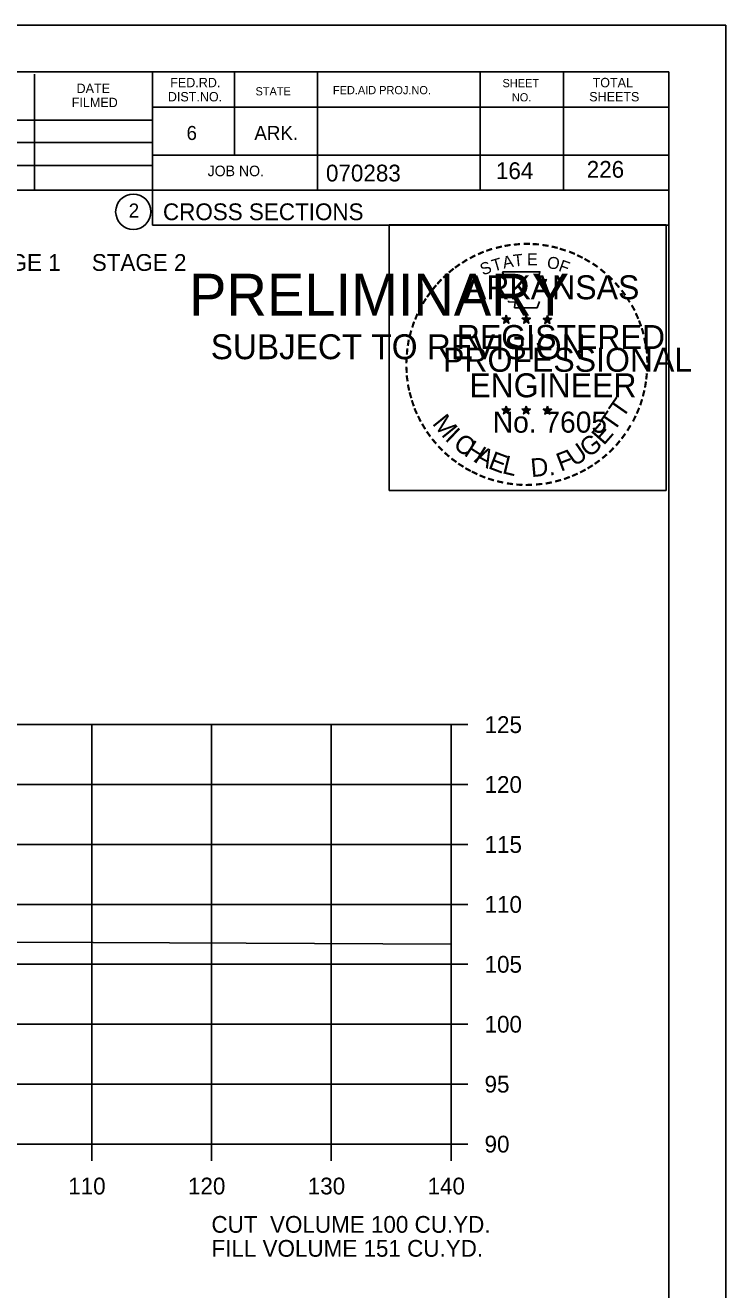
# Model space of a CAD drawing. Extents: x 1175611 to 1176402, y -433344 to -416213.
# Drawn here: x 1175885.4 to 1175943.9, y -429609 to -429503.4 of the extents above; entities that cross this region are included whole.
import ezdxf

# ---------------------------------------------------------------- set-up
doc = ezdxf.new("R2010")
doc.units = 0
for name, color, linetype in [('Default', 7, 'Continuous'), ('R_Axis', 7, 'Continuous'), ('R_Axis Annot', 7, 'Continuous'), ('R_Border', 7, 'Continuous'), ('R_Border Notes', 7, 'Continuous'), ('R_Border PE', 7, 'Continuous'), ('R_Border Prem', 7, 'Continuous'), ('R_Exist Surface', 7, 'Continuous'), ('R_Grid', 7, 'Continuous'), ('R_No Plot', 7, 'Continuous')]:
    doc.layers.add(name, color=color, linetype=linetype)

msp = doc.modelspace()

# ---------------------------------------------------------------- linework, layer by layer
at = {"layer": 'R_Axis'}
for p, q in [((1175920.97, -429596.8), (1175920.97, -429561.8)), ((1175922.37, -429561.8), (1175920.97, -429561.8)), ((1175922.37, -429566.8), (1175920.97, -429566.8)), ((1175922.37, -429571.8), (1175920.97, -429571.8)), ((1175922.37, -429576.8), (1175920.97, -429576.8)), ((1175922.37, -429581.8), (1175920.97, -429581.8)), ((1175922.37, -429586.8), (1175920.97, -429586.8)), ((1175922.37, -429591.8), (1175920.97, -429591.8)), ((1175640.97, -429596.8), (1175920.97, -429596.8)), ((1175890.97, -429598.2), (1175890.97, -429596.8)), ((1175900.97, -429598.2), (1175900.97, -429596.8)), ((1175910.97, -429598.2), (1175910.97, -429596.8)), ((1175920.97, -429598.2), (1175920.97, -429596.8)), ((1175922.37, -429596.8), (1175920.97, -429596.8))]:
    msp.add_line(p, q, dxfattribs=at)
at = {"layer": 'R_Border'}
for p, q in [((1175622.97, -429507.34), (1175939.15, -429507.34)), ((1175886.19, -429517.22), (1175886.19, -429507.54)), ((1175896.05, -429507.34), (1175896.05, -429520.14)), ((1175902.89, -429507.34), (1175902.89, -429514.28)), ((1175909.83, -429507.34), (1175909.83, -429517.22)), ((1175923.41, -429507.34), (1175923.41, -429517.22)), ((1175930.35, -429507.34), (1175930.35, -429517.22)), ((1175939.15, -429712.8), (1175939.15, -429507.34)), ((1175939.15, -429510.28), (1175896.05, -429510.28)), ((1175939.15, -429510.26), (1175939.15, -429510.26)), ((1175856.89, -429511.36), (1175896.05, -429511.36)), ((1175856.89, -429513.22), (1175896.05, -429513.22)), ((1175939.15, -429514.28), (1175896.05, -429514.28)), ((1175899.01, -429514.28), (1175939.15, -429514.28)), ((1175856.89, -429515.16), (1175896.05, -429515.16)), ((1175939.15, -429517.22), (1175856.89, -429517.22)), ((1175896.05, -429520.14), (1175939.15, -429520.14))]:
    msp.add_line(p, q, dxfattribs=at)
msp.add_circle((1175894.44, -429519.01), 1.47, dxfattribs=at)
at = {"layer": 'R_Border PE'}
for p, q in [((1175925.23, -429527.9), (1175925.58, -429528.01)), ((1175925.23, -429527.9), (1175925.49, -429527.94)), ((1175925.23, -429527.9), (1175925.47, -429528.02)), ((1175925.37, -429528.31), (1175925.58, -429528.01)), ((1175925.37, -429528.31), (1175925.49, -429528.06)), ((1175925.58, -429527.64), (1175925.54, -429527.9)), ((1175925.58, -429528.01), (1175925.58, -429527.64)), ((1175925.58, -429527.64), (1175925.63, -429527.89)), ((1175925.93, -429527.9), (1175925.58, -429528.01)), ((1175925.8, -429528.31), (1175925.58, -429528.01)), ((1175925.93, -429527.9), (1175925.64, -429527.95)), ((1175925.8, -429528.31), (1175925.66, -429528.01)), ((1175925.93, -429527.9), (1175925.73, -429528)), ((1175926.9, -429527.9), (1175927.25, -429528.01)), ((1175926.9, -429527.9), (1175927.16, -429527.94)), ((1175926.9, -429527.9), (1175927.14, -429528.02)), ((1175927.04, -429528.31), (1175927.25, -429528.01)), ((1175927.04, -429528.31), (1175927.16, -429528.06)), ((1175927.25, -429527.64), (1175927.21, -429527.9)), ((1175927.25, -429528.01), (1175927.25, -429527.64)), ((1175927.25, -429527.64), (1175927.3, -429527.89)), ((1175927.6, -429527.9), (1175927.25, -429528.01)), ((1175927.47, -429528.31), (1175927.25, -429528.01)), ((1175927.6, -429527.9), (1175927.31, -429527.95)), ((1175927.47, -429528.31), (1175927.33, -429528.01)), ((1175927.6, -429527.9), (1175927.4, -429528)), ((1175928.67, -429527.91), (1175929.02, -429528.02)), ((1175928.67, -429527.91), (1175928.92, -429527.95)), ((1175928.67, -429527.91), (1175928.91, -429528.03)), ((1175928.8, -429528.32), (1175929.02, -429528.02)), ((1175929.02, -429527.66), (1175928.98, -429527.91)), ((1175929.02, -429528.02), (1175929.02, -429527.66)), ((1175929.02, -429527.66), (1175929.07, -429527.91)), ((1175929.36, -429527.91), (1175929.02, -429528.02)), ((1175929.23, -429528.32), (1175929.02, -429528.02)), ((1175929.36, -429527.91), (1175929.08, -429527.96)), ((1175929.23, -429528.32), (1175929.09, -429528.03)), ((1175929.36, -429527.91), (1175929.16, -429528.01)), ((1175925.37, -429528.31), (1175925.58, -429528.09)), ((1175925.8, -429528.31), (1175925.58, -429528.09)), ((1175927.04, -429528.31), (1175927.25, -429528.09)), ((1175927.47, -429528.31), (1175927.25, -429528.09)), ((1175928.8, -429528.32), (1175928.93, -429528.07)), ((1175928.8, -429528.32), (1175929.02, -429528.1)), ((1175929.23, -429528.32), (1175929.02, -429528.1)), ((1175925.58, -429535.22), (1175925.54, -429535.47)), ((1175925.58, -429535.58), (1175925.58, -429535.22)), ((1175925.58, -429535.22), (1175925.63, -429535.47)), ((1175927.25, -429535.22), (1175927.21, -429535.47)), ((1175927.25, -429535.58), (1175927.25, -429535.22)), ((1175927.25, -429535.22), (1175927.3, -429535.47)), ((1175929.02, -429535.23), (1175928.97, -429535.48)), ((1175929.02, -429535.59), (1175929.02, -429535.23)), ((1175929.02, -429535.23), (1175929.06, -429535.48)), ((1175925.23, -429535.47), (1175925.58, -429535.58)), ((1175925.23, -429535.47), (1175925.48, -429535.52)), ((1175925.23, -429535.47), (1175925.47, -429535.59)), ((1175925.36, -429535.88), (1175925.58, -429535.58)), ((1175925.36, -429535.88), (1175925.49, -429535.63)), ((1175925.36, -429535.88), (1175925.58, -429535.66)), ((1175925.93, -429535.47), (1175925.58, -429535.58)), ((1175925.79, -429535.88), (1175925.58, -429535.58)), ((1175925.79, -429535.88), (1175925.58, -429535.66)), ((1175925.93, -429535.47), (1175925.64, -429535.52)), ((1175925.79, -429535.88), (1175925.66, -429535.59)), ((1175925.93, -429535.47), (1175925.72, -429535.57)), ((1175926.9, -429535.47), (1175927.25, -429535.58)), ((1175926.9, -429535.47), (1175927.15, -429535.52)), ((1175926.9, -429535.47), (1175927.14, -429535.59)), ((1175927.03, -429535.88), (1175927.25, -429535.58)), ((1175927.03, -429535.88), (1175927.16, -429535.63)), ((1175927.03, -429535.88), (1175927.25, -429535.66)), ((1175927.6, -429535.47), (1175927.25, -429535.58)), ((1175927.46, -429535.88), (1175927.25, -429535.58)), ((1175927.46, -429535.88), (1175927.25, -429535.66)), ((1175927.6, -429535.47), (1175927.31, -429535.52)), ((1175927.46, -429535.88), (1175927.32, -429535.59)), ((1175927.6, -429535.47), (1175927.39, -429535.57)), ((1175928.67, -429535.48), (1175929.02, -429535.59)), ((1175928.67, -429535.48), (1175928.92, -429535.53)), ((1175928.67, -429535.48), (1175928.9, -429535.6)), ((1175928.8, -429535.89), (1175929.02, -429535.59)), ((1175928.8, -429535.89), (1175928.93, -429535.64)), ((1175928.8, -429535.89), (1175929.01, -429535.67)), ((1175929.23, -429535.89), (1175929.01, -429535.67)), ((1175929.36, -429535.48), (1175929.02, -429535.59)), ((1175929.23, -429535.89), (1175929.02, -429535.59)), ((1175929.36, -429535.48), (1175929.08, -429535.53)), ((1175929.23, -429535.89), (1175929.09, -429535.6)), ((1175929.36, -429535.48), (1175929.16, -429535.58))]:
    msp.add_line(p, q, dxfattribs=at)
for points in [[(1175925.28, -429524.02), (1175925.54, -429524.85)], [(1175928.79, -429524.94), (1175928.93, -429524.66), (1175928.24, -429524.68), (1175928.39, -429524.02), (1175925.28, -429524.02)], [(1175925.77, -429526.44), (1175925.77, -429526.53), (1175926.33, -429526.55), (1175926.28, -429527.02), (1175928.15, -429527.02), (1175928.35, -429526.49)], [(1175925.58, -429527.64), (1175925.8, -429528.31), (1175925.23, -429527.9), (1175925.93, -429527.9), (1175925.37, -429528.31), (1175925.58, -429527.64)], [(1175927.25, -429527.64), (1175927.47, -429528.31), (1175926.9, -429527.9), (1175927.6, -429527.9), (1175927.04, -429528.31), (1175927.25, -429527.64)], [(1175929.02, -429527.66), (1175929.23, -429528.32), (1175928.67, -429527.91), (1175929.36, -429527.91), (1175928.8, -429528.32), (1175929.02, -429527.66)], [(1175925.58, -429535.22), (1175925.79, -429535.88), (1175925.23, -429535.47), (1175925.93, -429535.47), (1175925.36, -429535.88), (1175925.58, -429535.22)], [(1175927.25, -429535.22), (1175927.46, -429535.88), (1175926.9, -429535.47), (1175927.6, -429535.47), (1175927.03, -429535.88), (1175927.25, -429535.22)], [(1175929.02, -429535.23), (1175929.23, -429535.89), (1175928.67, -429535.48), (1175929.36, -429535.48), (1175928.8, -429535.89), (1175929.02, -429535.23)]]:
    msp.add_lwpolyline(points, dxfattribs=at)
for centre, radius in [((1175925.58, -429528.01), 0.172), ((1175925.58, -429528.01), 0.145), ((1175925.58, -429528.01), 0.116), ((1175925.58, -429528.01), 0.0991), ((1175925.58, -429528.01), 0.0747), ((1175925.58, -429528.01), 0.0495), ((1175925.58, -429528.01), 0.0296), ((1175927.25, -429528.01), 0.172), ((1175927.25, -429528.01), 0.145), ((1175927.25, -429528.01), 0.116), ((1175927.25, -429528.01), 0.0991), ((1175927.25, -429528.01), 0.0747), ((1175927.25, -429528.01), 0.0495), ((1175927.25, -429528.01), 0.0296), ((1175929.02, -429528.02), 0.172), ((1175929.02, -429528.02), 0.145), ((1175929.02, -429528.02), 0.116), ((1175929.02, -429528.02), 0.0991), ((1175929.02, -429528.02), 0.0747), ((1175929.02, -429528.02), 0.0495), ((1175929.02, -429528.02), 0.0296), ((1175925.58, -429535.58), 0.172), ((1175925.58, -429535.58), 0.145), ((1175927.25, -429535.58), 0.172), ((1175927.25, -429535.58), 0.145), ((1175929.01, -429535.59), 0.172), ((1175929.01, -429535.59), 0.145), ((1175925.58, -429535.58), 0.116), ((1175925.58, -429535.58), 0.0991), ((1175925.58, -429535.58), 0.0747), ((1175925.58, -429535.58), 0.0495), ((1175925.58, -429535.58), 0.0296), ((1175927.25, -429535.58), 0.116), ((1175927.25, -429535.58), 0.0991), ((1175927.25, -429535.58), 0.0747), ((1175927.25, -429535.58), 0.0495), ((1175927.25, -429535.58), 0.0296), ((1175929.01, -429535.59), 0.116), ((1175929.01, -429535.59), 0.0991), ((1175929.01, -429535.59), 0.0747), ((1175929.01, -429535.59), 0.0495), ((1175929.01, -429535.59), 0.0296)]:
    msp.add_circle(centre, radius, dxfattribs=at)
at = {"layer": 'R_Exist Surface'}
msp.add_lwpolyline([(1175827.66, -429580.31), (1175828.73, -429580.43), (1175841.16, -429581.94), (1175848.1, -429580.68), (1175852.72, -429579.81), (1175903.88, -429580.04), (1175920.97, -429580.12)], dxfattribs=at)
at = {"layer": 'R_Grid'}
for p, q in [((1175640.97, -429561.8), (1175920.97, -429561.8)), ((1175890.97, -429596.8), (1175890.97, -429561.8)), ((1175900.97, -429596.8), (1175900.97, -429561.8)), ((1175910.97, -429596.8), (1175910.97, -429561.8)), ((1175920.97, -429596.8), (1175920.97, -429561.8)), ((1175640.97, -429566.8), (1175920.97, -429566.8)), ((1175640.97, -429571.8), (1175920.97, -429571.8)), ((1175640.97, -429576.8), (1175920.97, -429576.8)), ((1175640.97, -429581.8), (1175920.97, -429581.8)), ((1175640.97, -429586.8), (1175920.97, -429586.8)), ((1175640.97, -429591.8), (1175920.97, -429591.8)), ((1175640.97, -429596.8), (1175920.97, -429596.8))]:
    msp.add_line(p, q, dxfattribs=at)
at = {"layer": 'R_No Plot'}
msp.add_line((1175610.57, -429503.45), (1175943.91, -429503.45), dxfattribs=at)
for points in [[(1175610.57, -429503.45), (1175943.91, -429503.45), (1175943.91, -429716.79), (1175610.57, -429716.79)], [(1175915.82, -429520.11), (1175938.92, -429520.11), (1175938.92, -429542.26), (1175915.82, -429542.26)]]:
    msp.add_lwpolyline(points, close=True, dxfattribs=at)

# ---------------------------------------------------------------- texts
at = {"layer": 'Default'}
for s, p in [('STAGE 1     STAGE 2', (1175880.47, -429523.94)), ('CUT  VOLUME 100 CU.YD.', (1175900.97, -429604.2)), ('FILL VOLUME 151 CU.YD.', (1175900.97, -429606.2))]:
    msp.add_text(s, height=1.4, dxfattribs=at).set_placement(p)
at = {"layer": 'R_Axis Annot'}
for s, p in [('125', (1175923.77, -429562.5)), ('120', (1175923.77, -429567.5)), ('115', (1175923.77, -429572.5)), ('110', (1175923.77, -429577.5)), ('105', (1175923.77, -429582.5)), ('100', (1175923.77, -429587.5)), ('95', (1175923.77, -429592.5)), ('90', (1175923.77, -429597.5)), ('110', (1175889.01, -429601)), ('120', (1175899.01, -429601)), ('130', (1175909.01, -429601)), ('140', (1175919.01, -429601))]:
    msp.add_text(s, height=1.4, dxfattribs=at).set_placement(p)
at = {"layer": 'R_Border'}
for s, height, p in [('FED.RD.', 0.782, (1175897.53, -429508.62)), ('SHEET', 0.684, (1175925.27, -429508.62)), ('TOTAL', 0.782, (1175932.79, -429508.62)), ('DATE', 0.782, (1175889.71, -429509.1)), ('DIST.NO.', 0.782, (1175897.33, -429509.8)), ('STATE', 0.684, (1175904.65, -429509.3)), ('FED.AID PROJ.NO.', 0.684, (1175911.11, -429509.2)), ('SHEETS', 0.782, (1175932.51, -429509.8)), ('FILMED', 0.782, (1175889.31, -429510.28)), ('NO.', 0.684, (1175926.05, -429509.8)), ('6', 1.17, (1175898.89, -429513.02)), ('ARK.', 1.172, (1175904.55, -429513.02)), ('JOB NO.', 0.879, (1175900.65, -429516.04)), ('070283', 1.4, (1175910.53, -429516.48)), ('2', 1.17, (1175894.06, -429519.49)), ('CROSS SECTIONS', 1.4, (1175896.92, -429519.71))]:
    msp.add_text(s, height=height, rotation=360, dxfattribs=at).set_placement(p)
at = {"layer": 'R_Border Notes'}
for s, p in [('164', (1175924.72, -429516.28)), ('226', (1175932.3, -429516.17))]:
    msp.add_text(s, height=1.4, dxfattribs=at).set_placement(p)
at = {"layer": 'R_Border PE'}
for s, height, rotation, p in [('-', 1.6, 10.2193, (1175925.45, -429522.49)), ('-', 1.6, 5.8968, (1175926.18, -429522.38)), ('-', 1.6, 0.1862, (1175926.95, -429522.31)), ('-', 1.6, 357.743, (1175927.67, -429522.32)), ('-', 1.6, 352.1617, (1175928.42, -429522.38)), ('-', 1.6, 28.7918, (1175922.76, -429523.48)), ('-', 1.6, 24.3072, (1175923.39, -429523.16)), ('-', 1.6, 19.1761, (1175924.02, -429522.89)), ('-', 1.6, 13.6301, (1175924.77, -429522.65)), ('A', 1, 11.2132, (1175925.37, -429523.76)), ('T', 1, 6.0228, (1175926.22, -429523.59)), ('E', 1, 0.8323, (1175927.32, -429523.48)), ('O', 1, 350.4515, (1175928.93, -429523.69)), ('-', 1.6, 347.2049, (1175929.14, -429522.49)), ('-', 1.6, 342.3362, (1175929.77, -429522.65)), ('-', 1.6, 337.8551, (1175930.51, -429522.87)), ('-', 1.6, 334.1211, (1175931.14, -429523.14)), ('-', 1.6, 38.9507, (1175921.1, -429524.62)), ('-', 1.6, 36.2317, (1175921.58, -429524.24)), ('-', 1.6, 34.0636, (1175922.16, -429523.85)), ('S', 1, 21.594, (1175923.63, -429524.34)), ('T', 1, 16.4036, (1175924.54, -429524.01)), ('F', 1, 340.0707, (1175929.88, -429523.92)), ('-', 1.6, 329.6409, (1175931.72, -429523.42)), ('-', 1.6, 325.8627, (1175932.36, -429523.78)), ('-', 1.6, 320.5297, (1175932.97, -429524.21)), ('-', 1.6, 48.423, (1175920.22, -429525.52)), ('-', 1.6, 42.9622, (1175920.67, -429525.04)), ('ARKANSAS', 2, 360, (1175922.13, -429526.31)), ('-', 1.6, 315.5786, (1175933.57, -429524.7)), ('-', 1.6, 309.8797, (1175934.14, -429525.25)), ('-', 1.6, 54.2325, (1175919.41, -429526.57)), ('-', 1.6, 50.6142, (1175919.82, -429526)), ('-', 1.6, 306.6522, (1175934.66, -429525.85)), ('-', 1.6, 62.8713, (1175918.77, -429527.71)), ('-', 1.6, 58.0706, (1175919.08, -429527.1)), ('-', 1.4, 303.6753, (1175935.15, -429526.42)), ('-', 1.6, 299.6684, (1175935.47, -429527.02)), ('-', 1.6, 67.7743, (1175918.51, -429528.32)), ('DWB', 0.01, 360, (1175925.57, -429528.01)), ('DWB', 0.01, 360, (1175927.24, -429528.01)), ('DWB', 0.01, 360, (1175929, -429528.03)), ('-', 1.6, 294.6628, (1175935.79, -429527.64)), ('-', 1.6, 290.5728, (1175936.05, -429528.21)), ('-', 1.6, 75.461, (1175918.09, -429529.67)), ('-', 1.6, 72.3945, (1175918.29, -429528.95)), ('REGISTERED', 2, 360, (1175921.45, -429530.46)), ('-', 1.6, 285.1233, (1175936.28, -429528.79)), ('-', 1.6, 81.2013, (1175917.96, -429530.38)), ('-', 1.6, 280.5493, (1175936.48, -429529.54)), ('-', 1.6, 89.0622, (1175917.86, -429531.77)), ('-', 1.6, 85.1863, (1175917.89, -429531.07)), ('PROFESSIONAL', 2, 360, (1175920.3, -429532.36)), ('-', 1.6, 276.5962, (1175936.65, -429530.3)), ('-', 1.6, 274.3301, (1175936.71, -429531.03)), ('-', 1.6, 94.1959, (1175917.9, -429532.5)), ('-', 1.6, 269.9407, (1175936.74, -429531.66)), ('-', 1.6, 98.9479, (1175917.97, -429533.16)), ('ENGINEER', 2, 360, (1175922.49, -429534.49)), ('-', 1.6, 260.9953, (1175936.65, -429532.98)), ('-', 1.6, 263.5172, (1175936.72, -429532.32)), ('-', 1.6, 101.7149, (1175918.1, -429533.9)), ('-', 1.6, 105.4578, (1175918.27, -429534.49)), ('-', 1.6, 255.7626, (1175936.54, -429533.66)), ('-', 1.6, 109.0874, (1175918.48, -429535.12)), ('-', 1.6, 114.0643, (1175918.73, -429535.72)), ('T', 1.54, 55.055, (1175935.3, -429536.32)), ('-', 1.6, 247.8887, (1175936.14, -429535.05)), ('-', 1.6, 252.8681, (1175936.36, -429534.38)), ('-', 1.6, 115.7289, (1175919.04, -429536.34)), ('M', 1.54, 308.9175, (1175919.35, -429536.69)), ('No. 7605', 1.757, 360, (1175924.46, -429537.44)), ('DWB', 0.01, 360, (1175925.56, -429535.59)), ('DWB', 0.01, 360, (1175927.23, -429535.59)), ('DWB', 0.01, 360, (1175929, -429535.6)), ('T', 1.54, 55.055, (1175934.57, -429537.44)), ('-', 1.6, 244.6197, (1175935.87, -429535.68)), ('-', 1.6, 120.4471, (1175919.4, -429536.92)), ('-', 1.6, 125.8934, (1175919.8, -429537.48)), ('I', 1.54, 316.4636, (1175920.39, -429538.01)), ('E', 1.54, 48.7313, (1175933.72, -429538.56)), ('-', 1.6, 233.8452, (1175935.08, -429537.08)), ('-', 1.6, 239.0712, (1175935.48, -429536.43)), ('-', 1.6, 130.7181, (1175920.26, -429538.03)), ('-', 1.6, 134.2238, (1175920.78, -429538.58)), ('C', 1.54, 324.0197, (1175921.06, -429538.63)), ('H', 1.54, 327.5342, (1175921.97, -429539.29)), ('U', 1.54, 34.4052, (1175931.27, -429540.32)), ('G', 1.54, 38.2173, (1175932.47, -429539.58)), ('-', 1.6, 231.2538, (1175934.65, -429537.65)), ('-', 1.6, 138.9338, (1175921.3, -429539.04)), ('-', 1.6, 144.6463, (1175921.86, -429539.45)), ('A', 1.54, 332.5513, (1175922.83, -429539.83)), ('E', 1.54, 339.2068, (1175923.99, -429540.39)), ('L', 1.54, 346.2929, (1175925.18, -429540.81)), ('D.', 1.54, 5.2602, (1175927.68, -429541.15)), ('F', 1.54, 20.8202, (1175930.13, -429540.71)), ('-', 1.6, 221.0851, (1175933.65, -429538.72)), ('-', 1.6, 225.7653, (1175934.17, -429538.21)), ('-', 1.6, 148.0898, (1175922.42, -429539.82)), ('-', 1.6, 151.5704, (1175923, -429540.15)), ('-', 1.6, 154.6002, (1175923.52, -429540.39)), ('-', 1.6, 207.3568, (1175932.01, -429539.93)), ('-', 1.6, 212.2491, (1175932.56, -429539.58)), ('-', 1.6, 215.7363, (1175933.1, -429539.19)), ('-', 1.6, 158.5612, (1175924.15, -429540.65)), ('-', 1.6, 162.7983, (1175924.83, -429540.86)), ('-', 1.6, 167.5555, (1175925.55, -429541.02)), ('-', 1.6, 173.1155, (1175926.32, -429541.13)), ('-', 1.6, 176.5183, (1175927.07, -429541.19)), ('-', 1.6, 181.5918, (1175927.81, -429541.17)), ('-', 1.6, 185.8167, (1175928.62, -429541.09)), ('-', 1.6, 191.2858, (1175929.36, -429540.96)), ('-', 1.6, 195.4743, (1175930.09, -429540.76)), ('-', 1.6, 200.7184, (1175930.76, -429540.52)), ('-', 1.6, 204.2516, (1175931.38, -429540.25))]:
    msp.add_text(s, height=height, rotation=rotation, dxfattribs=at).set_placement(p)
at = {"layer": 'R_Border Prem'}
for s, height, p in [('PRELIMINARY', 3.5, (1175899.1, -429527.68)), ('DWB', 0.01, (1175899.85, -429525.83)), ('SUBJECT TO REVISION', 2.0751, (1175900.91, -429531.31))]:
    msp.add_text(s, height=height, rotation=360, dxfattribs=at).set_placement(p)

doc.saveas('drawing.dxf')
